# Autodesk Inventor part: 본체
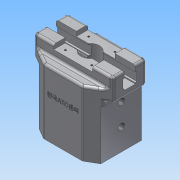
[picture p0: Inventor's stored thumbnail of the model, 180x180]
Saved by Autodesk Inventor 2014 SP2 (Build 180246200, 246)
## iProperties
Created: 2023-05
Part Number: 본체
Material: 알루미늄 6061
Document SubType Name: Modeling
Designer: 거성
Density: 2.71 g/cm^3
Appearance: 알루미늄 - 평지
Author: 거성
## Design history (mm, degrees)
sketch "스케치1"
  geometry: L1 (40, -35)-(-40, -35); L2 (-40, -35)-(-40, 35); L3 (-40, 35)-(40, 35); L4 (40, 35)-(40, -35); L5 (40, -35)-(-40, 35); L6 (-40, -35)-(40, 35); 1 further point
  constraints: 12 end point, 2 midpoint, 2 parallel, 1 horizontal, 1 perpendicular
  dimensions: "d9" = 80 distance of L2.end L3.end; "d10" = 70 distance of L1.end L2.end
extrude "돌출1" new body sketch "스케치1" stored distance "d11" = 70; taper "d12" = 0 deg
sketch "스케치4"
  geometry: L1 (-35, -35)-(-35, 35) reference; L2 (-35, 35)-(35, 35) reference; L3 (35, 35)-(35, -35) reference; L4 (35, -35)-(-35, -35) reference; L5 (35, 35)-(35, -35); L6 (35, -35)-(49, -35); L7 (49, -35)-(49, -22); L8 (49, -22)-(64, -22); L9 (64, -22)-(64, 22); L10 (64, 22)-(49, 22); L11 (49, 22)-(49, 35); L12 (49, 35)-(35, 35); 1 further point
  constraints: 16 end point, 4 parallel, 2 collinear, 2 equal length, 2 perpendicular
  dimensions: "d25" = 29 distance between parallel lines of L5 L9; "d26" = 44 distance of L8.end L9.end; "d27" = 15 distance of L7.end L8.end
extrude "돌출3" join sketch "스케치4" stored distance "d28" = 102; taper "d29" = 0 deg
sketch "스케치5"
  geometry: L1 (102, 44)-(102, 0) reference; L2 (0, -13)-(102, -13) reference; L3 (102, 0)-(102, -13) reference; L4 (0, 0)-(102, 0) reference; L5 (0, -13)-(0, 0) reference; L6 (0, 57)-(102, 57) reference; L7 (0, 44)-(102, 44) reference; L8 (102, 57)-(102, 44) reference; L9 (0, 57)-(102, 57) reference; L10 (0, 44)-(0, 57) reference; L11 (76.019, 57)-(102, 42); L12 (102, 2)-(76.019, -13); L13 (76.019, 57)-(102, 57); L14 (102, 57)-(102, 42); L15 (102, 2)-(102, -13); L16 (102, -13)-(76.019, -13); 1 further point
  constraints: 12 end point, 4 collinear, 4 point on line, 1 equal length
  dimensions: "d30" = 30 deg angle of L2 L11; "d31" = 30 deg angle of L6 L12; "d32" = 40 distance of L12.start L11.end
  node "투영된 루프1"
  node "투영된 루프2"
extrude "돌출4" cut sketch "스케치5" distance "d33" = 102; taper "d34" = 0 deg
sketch "스케치6"
  geometry: L1 (20, 64)-(-20, 64) reference; L2 (-20, 64)-(20, 64) reference; L3 (20, 64)-(20, 35) reference; L4 (20, 35)-(-20, 35) reference; L5 (-20, 35)-(-20, 64) reference; L6 (-7.2, 44.518)-(-9, 45); L7 (-9, 45)-(-9, 56); L8 (-9, 56)-(-7.2, 56.482); L9 (-7.2, 56.482)-(-7.2, 64); L10 (-7.2, 64)-(7.2, 64); L11 (7.2, 64)-(7.2, 56.482); L12 (7.2, 56.482)-(9, 56); L13 (9, 56)-(9, 45); L14 (9, 45)-(7.2, 44.518); L15 (-20, 35)-(20, 35) reference; L16 (-7.2, 44.518)-(-7.2, 43); L17 (-7.2, 43)-(7.2, 43); L18 (7.2, 43)-(7.2, 44.518); 5 further points
  constraints: 24 end point, 4 midpoint, 4 perpendicular, 3 equal length, 3 parallel, 2 point on line, 1 coincident, 1 vertical alignment
  dimensions: "d36" = 18 distance between parallel lines of L13 L7; "d37" = 8 vertical distance of L10.end L12.end; "d38" = 11 distance of L12.end L13.end; "d39" = 30 deg angle of L14 L12; "d40" = 14.4 distance between parallel lines of L11 L9; "d45" = 8 vertical distance of L7.end L9.end; "d47" = 30 deg angle of L6 L8; "d80" = 21 distance between parallel lines of L17 L1; "d81" = 1.51769 distance of L17.end L14.end
extrude "돌출5" cut sketch "스케치6" distance "d48" = 102; taper "d49" = 0 deg
sketch "스케치7"
  geometry: L1 (40, 35)-(40, -35) reference; L2 (40, -35)-(-40, -35) reference; L3 (-40, -35)-(-40, 35) reference; L4 (40, 35)-(40, -35) reference; L5 (40, -35)-(-40, -35) reference; L6 (-40, -35)-(-40, 35) reference; L7 (51, 64)-(51, 56.482) reference; L8 (-51, 64)-(51, 64) reference; L9 (-51, 56.482)-(-51, 64) reference; L10 (51, 56.482)-(-51, 56.482) reference; L11 (51, 56)-(51, 45) reference; L12 (51, 56)-(-51, 56) reference; L13 (-51, 45)-(-51, 56) reference; L14 (51, 45)-(-51, 45) reference; L15 (51, 44.518)-(51, 35) reference; L16 (51, 44.518)-(-51, 44.518) reference; L17 (-51, 35)-(-51, 44.518) reference; L18 (-40, 35)-(-51, 35) reference; L19 (40, 35)-(-40, 35) reference; L20 (51, 35)-(40, 35) reference; L21 (0, 64)-(0, -35); L22 (12, 64)-(12, 34); L23 (12, 34)-(8, 34); L24 (8, 34)-(8, 31.5); L25 (8, 31.5)-(10, 31.5); L26 (10, 31.5)-(10, 28.3); L27 (10, 28.3)-(8, 28.3); L28 (8, 28.3)-(8, 24); L29 (8, 24)-(25, 24); L30 (25, 24)-(25, -21); L31 (25, -21)-(30, -21); L32 (30, -21)-(30, -27); L33 (30, -27)-(31.5, -27); L34 (31.5, -27)-(31.5, -29.2); L35 (31.5, -29.2)-(30, -29.2); L36 (30, -29.2)-(30, -35); L37 (-51, 43)-(51, 43) reference; L38 (51, 43)-(51, 35) reference; L39 (51, 35)-(40, 35) reference; L40 (-40, 35)-(-51, 35) reference; L41 (-51, 35)-(-51, 43) reference; L42 (-51, 43)-(51, 43) reference; L43 (51, 43)-(51, 35) reference; L44 (51, 35)-(40, 35) reference; L45 (-40, 35)-(-51, 35) reference; L46 (-51, 35)-(-51, 43) reference; 1 further point
  constraints: 32 end point, 8 perpendicular, 7 parallel, 2 midpoint, 2 point on line
  dimensions: "d50" = 24 diameter of L22 L21; "d51" = 16 diameter of L24 L21; "d52" = 20 diameter of L26 L21; "d53" = 16 diameter of L28 L21; "d54" = 50 diameter of L30 L21; "d55" = 60 diameter of L32 L21; "d56" = 63 diameter of L34 L21; "d57" = 60 diameter of L36 L21; "d58" = 30 distance of L22.start L22.end; "d59" = 45 distance of L29.end L30.end; "d60" = 14 distance between parallel lines of L2 L31; "d61" = 2.2 distance of L33.end L34.end; "d62" = 6 distance of L31.end L32.end; "d63" = 3.2 distance of L25.end L26.end; "d65" = 2.5 distance of L23.end L24.end
revolve "회전1" sketch "스케치7" stored, may be unused: angle "d66" = 90 deg
sketch "스케치8"
  geometry: L1 (-95.072, 15)-(0, 15) reference; L2 (-72.536, 15)-(-22.536, 15); L3 (-22.536, 15)-(-22.536, 9); L4 (-22.536, 9)-(-72.536, 9); L5 (-72.536, 9)-(-72.536, 15); L6 (-72.536, 15)-(-22.536, 9); L7 (-22.536, 15)-(-72.536, 9); 3 further points
  constraints: 12 end point, 4 midpoint, 2 parallel, 1 horizontal, 1 perpendicular
  dimensions: "d67" = 50 distance of L3.end L4.end; "d68" = 6 distance of L2.end L3.end
extrude "돌출6" cut sketch "스케치8" stored distance "d69" = 102; taper "d70" = 0 deg
sketch "스케치9"
  geometry: L1 (0, 0)-(0, 70) reference; L2 (-52.702, 70)-(0, 70) reference; L3 (-33.551, 70)-(-19.151, 70) reference; L4 (-52.702, 70)-(0, 70) reference; L5 (-52.702, 70)-(-52.702, 0) reference; L6 (0, 0)-(-52.702, 0) reference; L7 (-52.702, 64)-(-52.702, 70); L8 (-52.702, 70)-(0, 70); L9 (0, 70)-(0, 64); L10 (0, 64)-(-52.702, 64); 1 further point
  constraints: 8 end point, 2 perpendicular, 2 point on line, 1 collinear
  dimensions: "d71" = 64 distance between parallel lines of L6 L10
extrude "돌출7" join sketch "스케치9" distance "d72" = 2; taper "d73" = 0 deg
extrude "돌출8" cut sketch "스케치5" stored distance "d74" = 2; taper "d75" = 0 deg
sketch "스케치10"
  geometry: L1 (15.4, -14.8)-(0, -14.8) reference; L2 (-4, -22)-(54, -22); L3 (-4, -28)-(54, -28); L4 (54, -16)-(-4, -16); A1 r 12 centre (25, -22) between (34.6, -14.8) and (15.4, -14.8) reference; A2 r 6 centre (-4, -22) between (-4, -16) and (-4, -28); A3 r 6 centre (54, -22) between (54, -28) and (54, -16)
  constraints: 8 end point, 4 point on circle, 4 tangent, 2 centre point, 2 parallel, 1 midpoint
  dimensions: "d76" = 12 distance between parallel lines of L3 L4; "d77" = 58 distance of L2.end L2.start
extrude "돌출9" cut sketch "스케치10" distance "d78" = 24; taper "d79" = 0 deg
sketch "스케치12"
  geometry: A1 r 12 centre (25, -22) between (34.6, -14.8) and (15.4, -14.8) reference; 1 further point
  dimensions: "d83" = 15 vertical distance of A1.centre point (8, -7); "d84" = 17 horizontal distance of A1.centre point (8, -7)
hole "구멍1" sketch "스케치12" at (8, -7) diameter "d85" = 2.459; stored, may be unused: countersink angle "d89" = 90 deg, drill point angle "d91" = 118 deg; dims "d86" = 6, "d87" = 4, "d88" = 2, "d90" = 8
sketch "스케치13"
  geometry: C1 r 30 at (0, 0) reference; 1 further point
  dimensions: "d92" = 26 horizontal distance of point (26, -25) C1.centre; "d93" = 25 vertical distance of C1.centre point (26, -25)
hole "구멍2" sketch "스케치13" at (26, -25) diameter "d94" = 4.917; stored, may be unused: countersink angle "d98" = 90 deg, drill point angle "d100" = 118 deg; dims "d95" = 12, "d96" = 4, "d97" = 2, "d99" = 14
sketch "스케치14"
  geometry: L1 (52.702, 0)-(0, 0) reference; 3 further points
  constraints: 2 vertical alignment
  dimensions: "d101" = 28 distance from line of L1 point (26.351, 28); "d102" = 28 distance of point (26.351, 28) point (26.351, 56)
hole "구멍3" sketch "스케치14" diameter "d103" = 4; stored, may be unused: countersink angle "d107" = 90 deg, drill point angle "d109" = 0 deg; dims "d104" = 12, "d105" = 4, "d106" = 2, "d108" = 14
hole "구멍4" sketch "스케치14" diameter "d110" = 8; stored, may be unused: countersink angle "d116" = 90 deg, drill point angle "d118" = 118 deg; dims "d111" = 9, "d112" = 0.62479, "d113" = 7.985, "d114" = 4, "d115" = 2, "d117" = 11
fillet "모깎기2" dims "d119" = 3
fillet "모깎기3" dims "d120" = 3
fillet "모깎기4" dims "d121" = 3
fillet "모깎기5" dims "d122" = 3
fillet "모깎기6" dims "d123" = 3
fillet "모깎기7" dims "d124" = 3
fillet "모깎기8" dims "d125" = 3
fillet "모깎기9" dims "d126" = 3
fillet "모깎기10" dims "d127" = 3
fillet "모깎기11" dims "d128" = 0.4
chamfer "모따기1" distance "d129" = 1; stored, may be unused: second distance "d130" = 2, angle "d131" = 45 deg
chamfer "모따기2" distance "d132" = 2; stored, may be unused: second distance "d133" = 2, angle "d134" = 20 deg
fillet "모깎기12" dims "d135" = 2
sketch "스케치15"
  geometry: L1 (49.215, 93)-(-0.785, 93) reference; L2 (-15.785, 67.804)-(-15.785, 0) reference; 2 further points
  constraints: 1 other
  dimensions: "d136" = 40 distance from line of L2 point (24.215, 53); "d137" = 40 distance from line of point (24.215, 53) L1
feature "엠보싱1" sketch "스케치15" dims "d138" = 0.5, "d139" = 0
node "솔리드1"
mirror "대칭2"
mirror "대칭3"
mirror "대칭4"
mirror "대칭5"
mirror "대칭6"
node "투영된 루프3"
node "투영된 루프4"
node "투영된 루프5"
node "절단 모서리 투영1"
node "절단 모서리 투영2"
node "절단 모서리 투영3"
node "절단 모서리 투영4"
